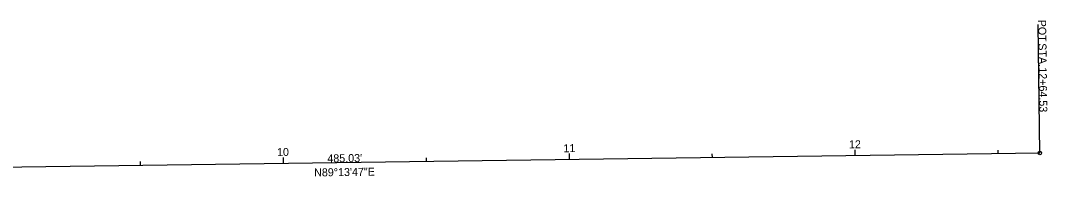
# Model space of a CAD drawing. Extents: x 1369241 to 1370511, y 405374 to 406419.
# Drawn here: x 1370152.1 to 1370511.3, y 405908.7 to 405963.3 of the extents above; entities that cross this region are included whole.
import ezdxf

# ---------------------------------------------------------------- set-up
doc = ezdxf.new("R2010")
doc.units = 0
for name, color, linetype in [('GE_P_Alignment_100_Bearings', 7, 'Continuous'), ('GE_P_Alignment_100_Cardinal_Points', 7, 'Continuous'), ('GE_P_Alignment_100_Distances', 7, 'Continuous'), ('GE_P_Alignment_100_Stations', 7, 'Continuous'), ('SG_P_Poles', 7, 'Continuous')]:
    doc.layers.add(name, color=color, linetype=linetype)

msp = doc.modelspace()

# ---------------------------------------------------------------- linework, layer by layer
at = {"layer": 'GE_P_Alignment_100_Cardinal_Points'}
msp.add_line((1370508.58, 405916.92), (1370507.97, 405961.91), dxfattribs=at)
msp.add_circle((1370508.58, 405916.92), 0.6, dxfattribs=at)
at = {"layer": 'GE_P_Alignment_100_Stations'}
for p, q in [((1370344.06, 405914.7), (1370344.03, 405916.7)), ((1370394.06, 405915.38), (1370394.04, 405916.58)), ((1370444.05, 405916.05), (1370444.02, 405918.05)), ((1370494.05, 405916.72), (1370494.03, 405917.92)), ((1370194.07, 405912.69), (1370194.06, 405913.89)), ((1370244.07, 405913.36), (1370244.04, 405915.36)), ((1370294.06, 405914.03), (1370294.05, 405915.23))]:
    msp.add_line(p, q, dxfattribs=at)
at = {"layer": 'SG_P_Poles'}
msp.add_line((1370023.59, 405910.4), (1370508.58, 405916.92), dxfattribs=at)

# ---------------------------------------------------------------- texts
at = {"layer": 'GE_P_Alignment_100_Bearings'}
msp.add_text('N89°13\'47"E', height=2.8, rotation=0.7703, dxfattribs=at).set_placement((1370254.79, 405908.7))
at = {"layer": 'GE_P_Alignment_100_Cardinal_Points'}
for s, p in [('POT', (1370507.99, 405963.52)), (' STA. ', (1370508.09, 405956.32)), ('12+64.53', (1370508.22, 405946.87))]:
    msp.add_text(s, height=2.8, rotation=270.7703, dxfattribs=at).set_placement(p)
at = {"layer": 'GE_P_Alignment_100_Distances'}
msp.add_text("485.03'", height=2.8, rotation=0.7703, dxfattribs=at).set_placement((1370259.41, 405913.61))
at = {"layer": 'GE_P_Alignment_100_Stations'}
for s, p in [('11', (1370341.99, 405917.18)), ('12', (1370441.85, 405918.52)), ('10', (1370241.81, 405915.83))]:
    msp.add_text(s, height=2.8, rotation=0.7703, dxfattribs=at).set_placement(p)

doc.saveas('drawing.dxf')
